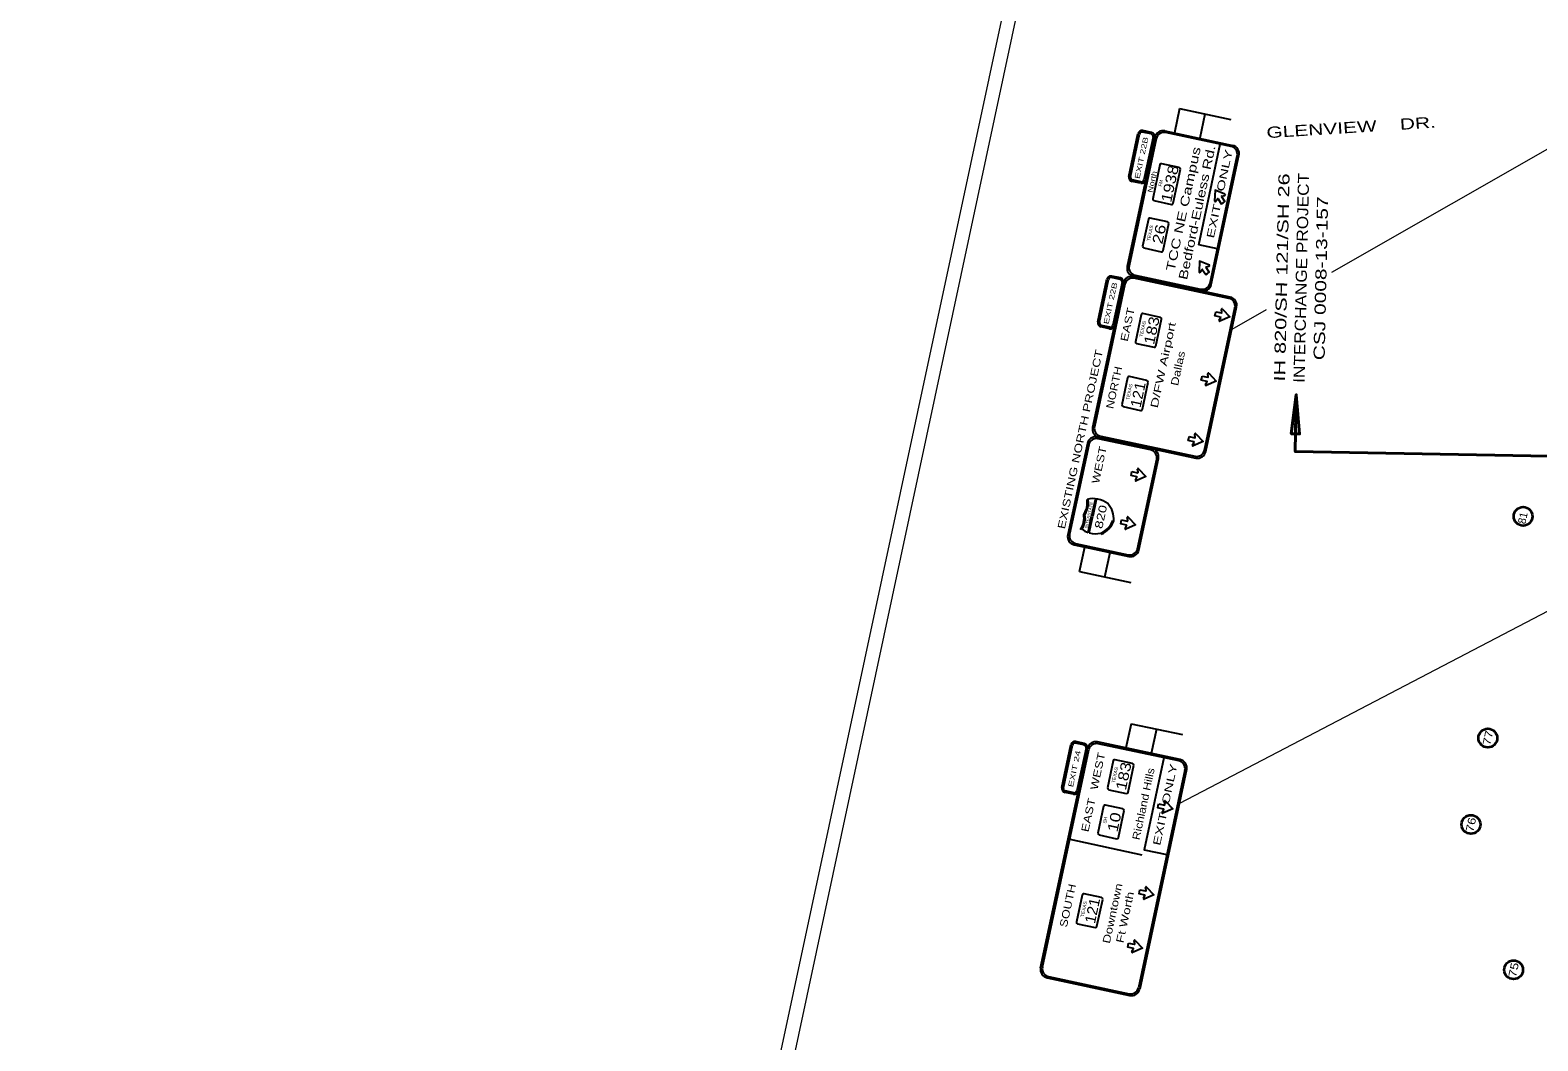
# Model space of a CAD drawing. Extents: x 2363411 to 2369702, y 6977197 to 6988655.
# Drawn here: x 2363411 to 2366110, y 6984259 to 6986070 of the extents above; entities that cross this region are included whole.
import ezdxf
from ezdxf.enums import TextEntityAlignment as Align

# ---------------------------------------------------------------- set-up
doc = ezdxf.new("R2010")
doc.units = 0
doc.header["$LTSCALE"] = 5.6
for name, color, linetype, lineweight in [('1', 7, 'Continuous', 25), ('10', 7, 'Continuous', 13), ('13', 7, 'Continuous', 13), ('17', 7, 'Continuous', 35), ('53', 7, 'Continuous', 40)]:
    doc.layers.add(name, color=color, linetype=linetype, lineweight=lineweight)

msp = doc.modelspace()

# ---------------------------------------------------------------- linework, layer by layer
at = {"layer": '1', "lineweight": 13}
for p, q in [((2366399.268, 6986012.095), (2365740.837, 6985635.417)), ((2365624.251, 6985568.72), (2365562.563, 6985533.429)), ((2366317.492, 6985128.147), (2365468.744, 6984684.533))]:
    msp.add_line(p, q, dxfattribs=at)
at = {"layer": '1'}
for p, q in [((2365468.894, 6985929.127), (2365459.683, 6985885.725)), ((2365468.894, 6985929.127), (2365560.878, 6985909.604)), ((2365514.281, 6985919.494), (2365505.069, 6985876.093)), ((2365424.791, 6985877.797), (2365375.355, 6985646.422)), ((2365378.243, 6985807.644), (2365394.466, 6985883.948)), ((2365380.992, 6985807.059), (2365397.213, 6985883.362)), ((2365417.892, 6985883.761), (2365402.775, 6985886.975)), ((2365418.477, 6985886.509), (2365403.361, 6985889.722)), ((2365421.504, 6985878.2), (2365405.273, 6985801.897)), ((2365442.645, 6985889.365), (2365564.093, 6985863.417)), ((2365563.628, 6985860.625), (2365443.899, 6985886.208)), ((2365427.157, 6985875.368), (2365378.508, 6985647.672)), ((2365503.485, 6985685.224), (2365541.959, 6985865.255)), ((2365433.823, 6985828.349), (2365420.926, 6985767.669)), ((2365468.396, 6985823.87), (2365437.164, 6985830.511)), ((2365523.53, 6985616.686), (2365572.219, 6985844.565)), ((2365525.829, 6985613.957), (2365575.265, 6985845.332)), ((2365399.127, 6985795.537), (2365384.019, 6985798.75)), ((2365399.714, 6985798.286), (2365384.603, 6985801.498)), ((2365457.66, 6985759.855), (2365470.557, 6985820.536)), ((2365544.824, 6985772.498), (2365550.233, 6985773.756)), ((2365423.089, 6985764.335), (2365454.32, 6985757.692)), ((2365533.633, 6985762.988), (2365536.966, 6985767.41)), ((2365538.061, 6985767.38), (2365538.08, 6985767.365)), ((2365413.142, 6985731.079), (2365402.9, 6985682.927)), ((2365447.714, 6985726.607), (2365416.483, 6985733.25)), ((2365439.634, 6985675.115), (2365449.876, 6985723.266)), ((2365405.071, 6985679.588), (2365436.301, 6985672.951)), ((2365536.659, 6985678.135), (2365503.485, 6985685.224)), ((2365505.653, 6985636.248), (2365508.987, 6985640.671)), ((2365510.082, 6985640.641), (2365510.1, 6985640.625)), ((2365516.845, 6985645.76), (2365522.253, 6985647.017)), ((2365368.794, 6985617.092), (2365313.392, 6985357.775)), ((2365371.153, 6985614.685), (2365316.609, 6985359.395)), ((2365322.718, 6985547.176), (2365339.021, 6985623.455)), ((2365325.464, 6985546.587), (2365341.76, 6985622.874)), ((2365362.44, 6985623.238), (2365347.333, 6985626.466)), ((2365363.027, 6985625.995), (2365347.92, 6985629.222)), ((2365366.037, 6985617.683), (2365349.742, 6985541.395)), ((2365386.922, 6985628.555), (2365493.255, 6985605.843)), ((2365559.654, 6985591.653), (2365386.927, 6985628.561)), ((2365557.232, 6985589.292), (2365387.13, 6985625.628)), ((2365389.358, 6985630.925), (2365506.785, 6985605.837)), ((2365400.19, 6985559.848), (2365389.909, 6985511.707)), ((2365434.757, 6985555.343), (2365403.532, 6985562.017)), ((2365513.508, 6985317.303), (2365568.051, 6985572.601)), ((2365515.869, 6985314.881), (2365571.194, 6985573.84)), ((2365533.992, 6985565.409), (2365544.152, 6985563.24)), ((2365540.076, 6985550.133), (2365543.012, 6985554.84)), ((2365544.97, 6985564.009), (2365544.209, 6985569.487)), ((2365343.598, 6985535.042), (2365328.491, 6985538.268)), ((2365344.187, 6985537.781), (2365329.072, 6985541.016)), ((2365426.635, 6985503.859), (2365436.916, 6985552)), ((2365392.068, 6985508.363), (2365423.293, 6985501.691)), ((2365376.064, 6985446.914), (2365365.776, 6985398.772)), ((2365410.631, 6985442.409), (2365379.406, 6985449.081)), ((2365509.384, 6985450.213), (2365519.544, 6985448.037)), ((2365520.355, 6985448.806), (2365519.593, 6985454.283)), ((2365402.502, 6985390.923), (2365412.79, 6985439.065)), ((2365515.461, 6985434.939), (2365518.398, 6985439.644)), ((2365367.942, 6985395.429), (2365399.166, 6985388.764)), ((2365321.758, 6985341.029), (2365498.062, 6985303.357)), ((2365419.678, 6985320.106), (2365321.758, 6985341.029)), ((2365328.237, 6985342.512), (2365496.817, 6985306.499)), ((2365486.24, 6985341.883), (2365496.399, 6985339.706)), ((2365497.211, 6985340.475), (2365496.449, 6985345.953)), ((2365303.952, 6985329.498), (2365268.96, 6985165.735)), ((2365306.312, 6985327.076), (2365272.103, 6985166.98)), ((2365417.256, 6985317.753), (2365323.004, 6985337.887)), ((2365492.316, 6985326.608), (2365495.252, 6985331.313)), ((2365393.865, 6985140.967), (2365428.068, 6985301.062)), ((2365396.226, 6985138.545), (2365431.209, 6985302.308)), ((2365383.782, 6985279.196), (2365393.941, 6985277.02)), ((2365389.851, 6985263.921), (2365392.796, 6985268.611)), ((2365394.752, 6985277.781), (2365393.984, 6985283.266)), ((2365317.9, 6985228.66), (2365311.633, 6985199.323)), ((2365319.792, 6985228.449), (2365313.483, 6985198.922)), ((2365305.367, 6985169.985), (2365311.633, 6985199.323)), ((2365307.176, 6985169.387), (2365313.483, 6985198.922)), ((2365365.289, 6985192.608), (2365375.447, 6985190.439)), ((2365371.357, 6985177.341), (2365374.302, 6985182.031)), ((2365376.26, 6985191.201), (2365375.49, 6985196.685)), ((2365282.93, 6985150.29), (2365377.181, 6985130.155)), ((2365280.506, 6985147.938), (2365378.426, 6985127.013)), ((2365289.834, 6985100.269), (2365299.164, 6985143.645)), ((2365335.194, 6985090.512), (2365344.523, 6985133.888)), ((2365289.834, 6985100.269), (2365381.764, 6985080.495)), ((2365382.105, 6984827.362), (2365372.894, 6984783.96)), ((2365382.105, 6984827.362), (2365474.09, 6984807.84)), ((2365427.492, 6984817.729), (2365418.28, 6984774.328)), ((2365220.29, 6984390.11), (2365304.276, 6984783.211)), ((2365223.432, 6984391.356), (2365306.607, 6984780.796)), ((2365258.2, 6984713.289), (2365274.495, 6984789.578)), ((2365260.947, 6984712.701), (2365277.242, 6984788.988)), ((2365297.92, 6984789.36), (2365282.807, 6984792.589)), ((2365298.509, 6984792.115), (2365283.394, 6984795.343)), ((2365301.528, 6984783.797), (2365285.223, 6984707.516)), ((2365470.206, 6984763.098), (2365322.067, 6984794.742)), ((2365467.784, 6984760.745), (2365323.313, 6984791.609)), ((2365350.331, 6984760.77), (2365340.042, 6984712.627)), ((2365384.89, 6984756.263), (2365353.666, 6984762.936)), ((2365376.769, 6984704.779), (2365387.05, 6984752.921)), ((2365481.722, 6984745.299), (2365397.761, 6984352.192)), ((2365478.581, 6984744.045), (2365395.402, 6984354.613)), ((2365279.071, 6984701.155), (2365263.965, 6984704.39)), ((2365279.659, 6984703.91), (2365264.553, 6984707.139)), ((2365342.202, 6984709.284), (2365373.426, 6984702.619)), ((2365333, 6984679.631), (2365322.72, 6984631.481)), ((2365367.575, 6984675.133), (2365336.336, 6984681.804)), ((2365359.447, 6984623.64), (2365369.727, 6984671.79)), ((2365431.775, 6984683.931), (2365441.927, 6984681.761)), ((2365437.844, 6984668.655), (2365440.788, 6984673.353)), ((2365442.737, 6984682.531), (2365441.977, 6984688.001)), ((2365272.344, 6984620.372), (2365401.689, 6984592.731)), ((2365324.873, 6984628.145), (2365356.104, 6984621.474)), ((2365398.09, 6984529.997), (2365408.244, 6984527.827)), ((2365409.054, 6984528.596), (2365408.294, 6984534.066)), ((2365294.651, 6984520.553), (2365284.356, 6984472.396)), ((2365329.218, 6984516.032), (2365297.987, 6984522.712)), ((2365321.091, 6984464.547), (2365331.386, 6984512.698)), ((2365404.161, 6984514.721), (2365407.105, 6984519.419)), ((2365286.523, 6984469.06), (2365317.755, 6984462.38)), ((2365377.69, 6984434.521), (2365387.844, 6984432.351)), ((2365383.761, 6984419.245), (2365386.705, 6984423.944)), ((2365388.654, 6984433.121), (2365387.894, 6984438.59)), ((2365231.825, 6984372.31), (2365379.119, 6984340.837)), ((2365234.247, 6984374.671), (2365378.712, 6984343.799))]:
    msp.add_line(p, q, dxfattribs=at)
for points in [[(2365550.33, 6985775.695), (2365532.553, 6985782.853), (2365531.816, 6985763.687)], [(2365538.08, 6985767.365), (2365543.729, 6985758.647), (2365546.897, 6985760.71), (2365550.069, 6985762.759), (2365544.417, 6985771.476)], [(2365522.352, 6985648.956), (2365504.573, 6985656.114), (2365503.836, 6985636.949)], [(2365510.1, 6985640.625), (2365515.749, 6985631.907), (2365518.916, 6985633.971), (2365522.088, 6985636.019), (2365516.439, 6985644.736)], [(2365542.577, 6985555.85), (2365532.417, 6985558.018), (2365533.205, 6985561.709), (2365533.992, 6985565.409)], [(2365545.988, 6985570.269), (2365559.012, 6985556.195), (2365541.38, 6985548.694)], [(2365517.962, 6985440.655), (2365507.802, 6985442.824), (2365508.596, 6985446.515), (2365509.384, 6985450.213)], [(2365521.372, 6985455.074), (2365534.396, 6985441), (2365516.764, 6985433.491)], [(2365494.817, 6985332.324), (2365484.656, 6985334.493), (2365485.452, 6985338.185), (2365486.24, 6985341.883)], [(2365498.228, 6985346.743), (2365511.252, 6985332.67), (2365493.62, 6985325.161)], [(2365395.763, 6985284.055), (2365408.786, 6985269.974), (2365391.154, 6985262.473)], [(2365392.36, 6985269.63), (2365382.2, 6985271.799), (2365382.988, 6985275.489), (2365383.782, 6985279.196)], [(2365373.866, 6985183.05), (2365363.706, 6985185.218), (2365364.494, 6985188.909), (2365365.289, 6985192.608)], [(2365377.268, 6985197.475), (2365390.292, 6985183.394), (2365372.661, 6985175.886)], [(2365440.62, 6984766.548), (2365405.406, 6984601.682), (2365446.307, 6984592.941)], [(2365440.351, 6984674.372), (2365430.193, 6984676.533), (2365430.989, 6984680.217), (2365431.775, 6984683.931)], [(2365443.756, 6984688.782), (2365456.779, 6984674.724), (2365439.14, 6984667.207)], [(2365406.668, 6984520.438), (2365396.51, 6984522.598), (2365397.305, 6984526.283), (2365398.09, 6984529.997)], [(2365410.072, 6984534.848), (2365423.095, 6984520.79), (2365405.457, 6984513.272)], [(2365386.268, 6984424.963), (2365376.11, 6984427.124), (2365376.905, 6984430.808), (2365377.69, 6984434.521)], [(2365389.672, 6984439.373), (2365402.695, 6984425.315), (2365385.057, 6984417.798)]]:
    msp.add_lwpolyline(points, dxfattribs=at)
for centre, radius, start, end in [((2365401.803, 6985882.387), 7.501, 77.99433, 167.99433), ((2365401.803, 6985882.387), 4.688, 77.99433, 167.99433), ((2365416.917, 6985879.173), 4.688, 347.99433, 77.99433), ((2365417.454, 6985879.357), 7.501, 347.99433, 77.99433), ((2365439.507, 6985874.653), 15.049, 77.93925, 169.35675), ((2365440.954, 6985872.42), 14.108, 77.93925, 167.93925), ((2365558.422, 6985847.513), 14.108, 347.93925, 68.3439), ((2365560.616, 6985848.776), 15.049, 346.76968, 76.63979), ((2365436.576, 6985827.761), 2.813, 77.99516, 167.99516), ((2365467.81, 6985821.12), 2.813, 347.99516, 77.99516), ((2365385.577, 6985806.086), 7.501, 167.99433, 257.99433), ((2365385.577, 6985806.086), 4.688, 167.99433, 257.99433), ((2365401.16, 6985802.772), 7.501, 257.99433, 347.99433), ((2365400.69, 6985802.872), 4.688, 257.99433, 347.99433), ((2365544.973, 6985771.858), 0.675, 102.95611, 212.93922), ((2365549.983, 6985774.736), 1.012, 282.81958, 68.20072), ((2365423.671, 6985767.085), 2.813, 167.99516, 257.99516), ((2365454.905, 6985760.443), 2.813, 257.99516, 347.99516), ((2365532.821, 6985763.617), 1.012, 177.67771, 323.05885), ((2365537.495, 6985767.013), 0.675, 32.93922, 142.92232), ((2365415.892, 6985730.5), 2.813, 77.99516, 167.99516), ((2365447.126, 6985723.859), 2.813, 347.99516, 77.99516), ((2365405.65, 6985682.338), 2.813, 167.99516, 257.99516), ((2365436.885, 6985675.696), 2.813, 257.99516, 347.99516), ((2365390.072, 6985643.277), 15.049, 167.93925, 257.93925), ((2365392.304, 6985644.724), 14.108, 167.93925, 257.93925), ((2365504.842, 6985636.877), 1.012, 177.67771, 323.05885), ((2365509.515, 6985640.274), 0.675, 32.93922, 142.92232), ((2365516.993, 6985645.119), 0.675, 102.95611, 212.93922), ((2365522.003, 6985647.996), 1.012, 282.81958, 68.20072), ((2365346.349, 6985621.887), 7.501, 77.94004, 167.94004), ((2365346.349, 6985621.887), 4.688, 77.94004, 167.94004), ((2365361.459, 6985618.659), 4.688, 347.94004, 77.94004), ((2365361.459, 6985618.659), 7.501, 347.94004, 77.94004), ((2365383.462, 6985613.962), 15.001, 76.65884, 167.94004), ((2365384.905, 6985611.744), 14.063, 80.89911, 167.94004), ((2365509.734, 6985619.633), 14.108, 257.93925, 347.93925), ((2365511.18, 6985617.401), 15.049, 257.93925, 346.76968), ((2365554.297, 6985575.532), 14.063, 347.94004, 77.94004), ((2365556.523, 6985576.974), 15.001, 347.94004, 77.94004), ((2365402.941, 6985559.266), 2.813, 77.94004, 167.94004), ((2365434.169, 6985552.594), 2.813, 347.94004, 77.94004), ((2365542.454, 6985555.191), 0.675, 327.95694, 77.94004), ((2365544.316, 6985563.905), 0.675, 257.94004, 7.92315), ((2365545.219, 6985569.612), 1.012, 42.67854, 188.05968), ((2365330.05, 6985545.602), 7.501, 167.94004, 257.94004), ((2365330.05, 6985545.602), 4.688, 167.94004, 257.94004), ((2365345.161, 6985542.374), 7.501, 257.94004, 347.94004), ((2365345.161, 6985542.374), 4.688, 257.94004, 347.94004), ((2365540.946, 6985549.614), 1.012, 147.82041, 293.20155), ((2365392.654, 6985511.113), 2.813, 167.94004, 257.94004), ((2365423.881, 6985504.441), 2.813, 257.94004, 347.94004), ((2365378.813, 6985446.332), 2.813, 77.94004, 167.94004), ((2365519.704, 6985448.708), 0.675, 257.94004, 7.92315), ((2365520.607, 6985454.414), 1.012, 42.67854, 188.05968), ((2365410.041, 6985439.66), 2.813, 347.94004, 77.94004), ((2365516.334, 6985434.417), 1.012, 147.82041, 293.20155), ((2365517.842, 6985439.994), 0.675, 327.95694, 77.94004), ((2365368.525, 6985398.179), 2.813, 167.94004, 257.94004), ((2365399.753, 6985391.507), 2.813, 257.94004, 347.94004), ((2365318.622, 6985326.36), 15.001, 77.94004, 167.94004), ((2365320.064, 6985324.135), 14.063, 77.94004, 167.94004), ((2365328.058, 6985354.641), 15.001, 167.94004, 245.1661), ((2365330.362, 6985356.449), 14.063, 167.94004, 257.94004), ((2365496.559, 6985340.377), 0.675, 257.94004, 7.92315), ((2365497.462, 6985346.084), 1.012, 42.67854, 188.05968), ((2365414.316, 6985303.998), 14.063, 347.94004, 77.94004), ((2365416.541, 6985305.44), 15.001, 347.94004, 77.94004), ((2365493.19, 6985326.086), 1.012, 147.82041, 293.20155), ((2365494.697, 6985331.663), 0.675, 327.95694, 77.94004), ((2365499.755, 6985320.244), 14.063, 257.94004, 347.94004), ((2365501.197, 6985318.019), 15.001, 257.94004, 347.94004), ((2365395.002, 6985283.392), 1.012, 42.67854, 188.05968), ((2365390.73, 6985263.395), 1.012, 147.82041, 293.20155), ((2365392.238, 6985268.972), 0.675, 327.95694, 77.94004), ((2365394.099, 6985277.685), 0.675, 257.94004, 7.92315), ((2365314.585, 6985188.725), 41.954, 51.80322, 105.50559), ((2365267.929, 6985222.922), 35.984, 325.12042, 9.97073), ((2365267.929, 6985222.922), 37.874, 326.31833, 7.31517), ((2365310.593, 6985194.124), 40.698, 355.41193, 42.64783), ((2365262.098, 6985195.626), 35.984, 325.90933, 10.75964), ((2365262.098, 6985195.626), 37.874, 328.56489, 9.56173), ((2365312.805, 6985204.475), 38.808, 293.45561, 340.10199), ((2365312.805, 6985204.475), 40.698, 293.23223, 340.46813), ((2365372.236, 6985176.813), 1.012, 147.82041, 293.20155), ((2365373.744, 6985182.39), 0.675, 327.95694, 77.94004), ((2365375.606, 6985191.104), 0.675, 257.94004, 7.92315), ((2365376.509, 6985196.81), 1.012, 42.67854, 188.05968), ((2365283.641, 6985162.603), 15.001, 167.94004, 257.94004), ((2365285.866, 6985164.045), 14.063, 167.94004, 257.94004), ((2365318.654, 6985207.771), 40.064, 232.76565, 250.6304), ((2365318.654, 6985207.771), 40.064, 253.34833, 283.86031), ((2365380.118, 6985143.908), 14.063, 257.94004, 347.94004), ((2365381.56, 6985141.682), 15.001, 257.94004, 347.94004), ((2365281.831, 6984788.007), 7.501, 77.93922, 167.93922), ((2365281.831, 6984788.007), 4.688, 77.93922, 167.93922), ((2365296.941, 6984784.778), 4.688, 347.93922, 77.93922), ((2365296.941, 6984784.778), 7.501, 347.93922, 77.93922), ((2365318.938, 6984780.077), 15.001, 77.93966, 167.93966), ((2365320.38, 6984777.852), 14.063, 77.93966, 167.93966), ((2365353.075, 6984760.188), 2.813, 77.93856, 167.93856), ((2365384.303, 6984753.515), 2.813, 347.93856, 77.93856), ((2365464.845, 6984746.988), 14.063, 347.93966, 77.93966), ((2365467.071, 6984748.43), 15.001, 347.93966, 77.93966), ((2365265.531, 6984711.722), 7.501, 167.93922, 257.93922), ((2365265.531, 6984711.722), 4.688, 167.93922, 257.93922), ((2365280.641, 6984708.493), 7.501, 257.93922, 347.93922), ((2365280.641, 6984708.493), 4.688, 257.93922, 347.93922), ((2365342.786, 6984712.036), 2.813, 167.93856, 257.93856), ((2365374.014, 6984705.363), 2.813, 257.93856, 347.93856), ((2365335.754, 6984679.049), 2.813, 77.93966, 167.93966), ((2365366.982, 6984672.377), 2.813, 347.93966, 77.93966), ((2365438.72, 6984668.132), 1.012, 147.82003, 293.20117), ((2365440.228, 6984673.709), 0.675, 327.95656, 77.93966), ((2365442.089, 6984682.422), 0.675, 257.93966, 7.92277), ((2365442.992, 6984688.129), 1.012, 42.67816, 188.05929), ((2365325.466, 6984630.896), 2.813, 167.93966, 257.93966), ((2365356.693, 6984624.224), 2.813, 257.93966, 347.93966), ((2365408.406, 6984528.489), 0.675, 257.93966, 7.92277), ((2365409.309, 6984534.195), 1.012, 42.67816, 188.05929), ((2365297.402, 6984519.96), 2.813, 77.93906, 167.93906), ((2365328.63, 6984513.288), 2.813, 347.93906, 77.93906), ((2365405.036, 6984514.198), 1.012, 147.82003, 293.20117), ((2365406.544, 6984519.775), 0.675, 327.95656, 77.93966), ((2365287.113, 6984471.808), 2.813, 167.93906, 257.93906), ((2365318.341, 6984465.135), 2.813, 257.93906, 347.93906), ((2365386.144, 6984424.3), 0.675, 327.95656, 77.93966), ((2365388.006, 6984433.013), 0.675, 257.93966, 7.92277), ((2365388.908, 6984438.72), 1.012, 42.67816, 188.05929), ((2365384.636, 6984418.722), 1.012, 147.82003, 293.20117), ((2365234.959, 6984386.975), 15.001, 167.93908, 257.93908), ((2365237.185, 6984388.417), 14.063, 167.93908, 257.93908), ((2365381.649, 6984357.552), 14.063, 257.93908, 347.93908), ((2365383.091, 6984355.326), 15.001, 257.93908, 347.93908)]:
    msp.add_arc(centre, radius, start, end, dxfattribs=at)
at = {"layer": '1', "lineweight": 35}
msp.add_arc((2359877.328, 6985028.058), 6500, 337.9611, 358.49155, dxfattribs=at)
at = {"layer": '10'}
for p, q in [((2363411.416, 6977949.748), (2365605.51, 6988218.434)), ((2363435.864, 6977944.524), (2365629.958, 6988213.21))]:
    msp.add_line(p, q, dxfattribs=at)
at = {"layer": '17'}
for centre in [(2366084.002, 6985198.895), (2366020.872, 6984801.786), (2365990.627, 6984647.006), (2366066.978, 6984386.695)]:
    msp.add_circle(centre, 16.828, dxfattribs=at)
at = {"layer": '53'}
for points in [[(2365678.044, 6985416.643), (2365668.894, 6985346.837), (2365683.891, 6985346.482)], [(2365683.891, 6985346.482), (2365678.044, 6985416.643), (2365668.894, 6985346.837)]]:
    msp.add_lwpolyline(points, close=True, dxfattribs=at)
msp.add_lwpolyline([(2367072.309, 6985289.554), (2365676.205, 6985314.749), (2365678.044, 6985416.643)], dxfattribs=at)

# ---------------------------------------------------------------- texts
at = {"layer": '1'}
for s, height, rotation, width, p in [('EXIT 22B', 9.188, 77.994, 1.45, (2365405.264, 6985840.077)), ('TCC NE Campus', 15.68, 77.939, 1.4, (2365483.461, 6985747.905)), ('Bedford-Euless Rd.', 15.68, 77.939, 1.35, (2365507.867, 6985741.617)), ('EXIT   ONLY', 13.5, 77.939, 1.55, (2365547.168, 6985775.168)), ('North', 9.188, 77.994, 1.3, (2365424.59, 6985797.233)), ('EXIT 22B', 9.188, 77.94, 1.45, (2365349.768, 6985579.587)), ('EAST', 13.5, 77.94, 1.3, (2365382.395, 6985541.146)), ('D/FW Airport', 13.5, 77.94, 1.5, (2365445.998, 6985468.456)), ('EXISTING NORTH PROJECT', 13.5, 77.94, 1.35, (2365297.783, 6985335.494)), ('Dallas', 13.5, 77.94, 1.25, (2365472.63, 6985462.486)), ('NORTH', 13.5, 77.94, 1.2, (2365358.257, 6985428.204)), ('WEST', 13.5, 77.94, 1.3, (2365331.64, 6985289.661)), ('EXIT 24', 9.188, 77.939, 1.5, (2365285.253, 6984745.7)), ('WEST', 13.5, 77.939, 1.3, (2365329.019, 6984741.006)), ('Richland Hills', 13.5, 77.94, 1.2, (2365410.9, 6984682.416)), ('EXIT  ONLY', 13.5, 77.939, 1.5, (2365449.772, 6984681.161)), ('EAST', 13.5, 77.939, 1.3, (2365312.232, 6984662.443)), ('SOUTH', 13.5, 77.939, 1.25, (2365275.427, 6984500.334)), ('Downtown', 13.5, 77.94, 1.3, (2365355.492, 6984486.36)), ('Ft Worth', 13.5, 77.94, 1.35, (2365377.973, 6984479.377))]:
    msp.add_text(s, height=height, rotation=rotation, dxfattribs=dict(at, width=width)).set_placement(p, align=Align.CENTER)
for s, height, rotation, width, p in [('1938', 18.75, 77.995, 1.2, (2365453.923, 6985760.126)), ('TEXAS', 6, 77.995, 1.1, (2365416.014, 6985691.219)), ('26', 18.75, 77.995, 1.25, (2365438.024, 6985685.349)), ('183', 18.75, 77.94, 1.2, (2365423.154, 6985505.305)), ('TEXAS', 6, 77.94, 1.1, (2365403.024, 6985519.983)), ('TEXAS', 6, 77.94, 1.1, (2365378.898, 6985407.05)), ('121', 18.75, 77.94, 1.1, (2365399.028, 6985392.369)), ('INTERSTATE', 5.197, 77.94, 1.1, (2365304.487, 6985177.455)), ('820', 14.18, 77.94, 1.35, (2365330.558, 6985175.705)), ('TEXAS', 6, 77.939, 1.1, (2365353.164, 6984720.906)), ('183', 18.75, 77.939, 1.2, (2365372.76, 6984707.118)), ('10', 18.75, 77.94, 1.25, (2365357.636, 6984632.233)), ('TEXAS', 6, 77.939, 1.1, (2365297.486, 6984480.675)), ('121', 18.75, 77.939, 1.1, (2365317.383, 6984468.273))]:
    msp.add_text(s, height=height, rotation=rotation, dxfattribs=dict(at, width=width)).set_placement(p)
for s, rotation, p in [('FM', 77.995, (2365436.859, 6985789.258)), ('SH', 77.94, (2365337.675, 6984648.381))]:
    msp.add_text(s, height=6, rotation=rotation, dxfattribs=at).set_placement(p)
at = {"layer": '13', "width": 1.4}
msp.add_text('GLENVIEW    DR.', height=20, rotation=3.575, dxfattribs=at).set_placement((2365625.148, 6985876.246))
at = {"layer": '17'}
msp.add_text('81', height=14, rotation=77.939, dxfattribs=at).set_placement((2366090.219, 6985194.492), align=Align.CENTER)
at = {"layer": '17', "width": 1.25}
for s, p in [('77', (2366027.79, 6984800.672)), ('76', (2365997.4, 6984645.204)), ('75', (2366073.831, 6984385.265))]:
    msp.add_text(s, height=14, rotation=77.939, dxfattribs=at).set_placement(p, align=Align.CENTER)
at = {"layer": '53'}
for s, width, p in [('IH 820/SH 121/SH 26', 1.45, (2365661.917, 6985626.579)), ('INTERCHANGE PROJECT', 1.15, (2365696.908, 6985625.805)), ('CSJ 0008-13-157', 1.4, (2365731.899, 6985625.03))]:
    msp.add_text(s, height=20, rotation=88.733, dxfattribs=dict(at, width=width)).set_placement(p, align=Align.CENTER)

doc.saveas('drawing.dxf')
